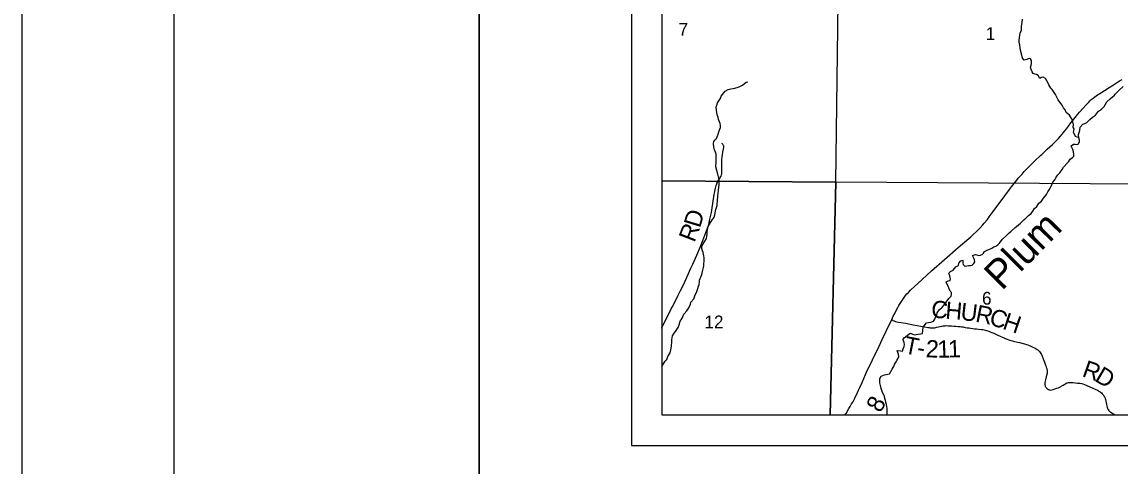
# Model space of a CAD drawing. Extents: x 0 to 34, y 0 to 22.
# Drawn here: x 0 to 3.604, y 13.932 to 15.391 of the extents above; entities that cross this region are included whole.
import ezdxf

# ---------------------------------------------------------------- set-up
doc = ezdxf.new("R2010")
doc.units = 0
for name, color, linetype in [('GM_X_Corporation', 7, 'Continuous'), ('GM_X_County_Road_Text', 7, 'Continuous'), ('GM_X_Interchange_Ramps', 7, 'Continuous'), ('GM_X_Interstate_Route', 7, 'Continuous'), ('GM_X_Major_Lake', 7, 'Continuous'), ('GM_X_Minor_Lake', 7, 'Continuous'), ('GM_X_Section', 7, 'Continuous'), ('GM_X_Township_Road_Text', 7, 'Continuous'), ('GM_X_Unincorporated_Text', 7, 'Continuous'), ('GM_X_US_Shield', 7, 'Continuous'), ('SH_Border', 7, 'Continuous'), ('SH_Cut_Line', 7, 'Continuous'), ('SH_Data', 7, 'Continuous')]:
    doc.layers.add(name, color=color, linetype=linetype)

msp = doc.modelspace()

# ---------------------------------------------------------------- linework, layer by layer
at = {"layer": 'GM_X_Corporation'}
for points in [[(2.8543, 14.4132), (2.8596, 14.424), (2.8643, 14.4338), (2.8689, 14.4433), (2.8739, 14.4525), (2.8782, 14.4597), (2.882, 14.4664), (2.8863, 14.4729), (2.8905, 14.479), (2.8952, 14.4859), (2.8998, 14.492), (2.9043, 14.4974), (2.9095, 14.5028), (2.9161, 14.5096), (2.9304, 14.5235), (2.9399, 14.5323), (2.9695, 14.5588), (2.9851, 14.5732), (3.0278, 14.6108), (3.0726, 14.6503), (3.0868, 14.6622), (3.1143, 14.6856), (3.1184, 14.6896), (3.1342, 14.7045), (3.1384, 14.7087), (3.1447, 14.7153), (3.1536, 14.7248), (3.158, 14.7299), (3.1683, 14.7424), (3.1744, 14.7504), (3.1878, 14.7686), (3.2255, 14.8198), (3.2405, 14.8403), (3.2473, 14.8493), (3.26, 14.8654), (3.2648, 14.8718), (3.2696, 14.8779), (3.2749, 14.8839), (3.282, 14.8914), (3.2895, 14.8995), (3.3142, 14.9252), (3.324, 14.935), (3.343, 14.9527), (3.3468, 14.9562), (3.365, 14.973), (3.3815, 14.9886), (3.3962, 15.0029), (3.4017, 15.0086), (3.4081, 15.0155), (3.4138, 15.022), (3.4183, 15.0275), (3.4225, 15.0332), (3.4275, 15.0399), (3.4343, 15.0491), (3.4423, 15.0599), (3.4473, 15.0666), (3.4646, 15.0882), (3.4707, 15.0951), (3.492, 15.1186), (3.4967, 15.1237), (3.5008, 15.1281), (3.5049, 15.1319), (3.5092, 15.1359), (3.5153, 15.1408), (3.5198, 15.1444), (3.5266, 15.1491), (3.5377, 15.1565), (3.5674, 15.1758), (3.5819, 15.185), (3.6016, 15.1975), (3.6101, 15.2025)], [(2.7012, 14.1), (2.7045, 14.1051), (2.7139, 14.1209), (2.7181, 14.1281), (2.7228, 14.1361), (2.7264, 14.1425), (2.7295, 14.148), (2.7332, 14.1551), (2.7422, 14.1734), (2.7457, 14.1809), (2.7499, 14.1902), (2.7569, 14.2063), (2.7684, 14.2334), (2.7714, 14.2407), (2.791, 14.2807), (2.8127, 14.3264), (2.8231, 14.3484), (2.836, 14.3748), (2.8543, 14.4132)]]:
    msp.add_lwpolyline(points, dxfattribs=at)
at = {"layer": 'GM_X_Interchange_Ramps'}
msp.add_lwpolyline([(2.1, 17.9098), (2.1, 14.1), (6.5113, 14.1), (6.5389, 15.3228), (6.5411, 15.4243), (6.5572, 16.1864), (6.5647, 16.5359), (6.5883, 17.471), (6.5943, 17.9356)], dxfattribs=at)
at = {"layer": 'GM_X_Interstate_Route'}
for points in [[(2.1, 14.3849), (2.1004, 14.3858), (2.131, 14.4482), (2.1359, 14.4579), (2.1537, 14.4931), (2.1604, 14.5068), (2.1683, 14.5234), (2.1749, 14.5375), (2.1955, 14.5819), (2.2015, 14.5954), (2.2143, 14.6251), (2.2263, 14.6537), (2.2343, 14.6731), (2.2444, 14.6989), (2.2488, 14.7105), (2.2511, 14.717), (2.2527, 14.7222), (2.2551, 14.7314), (2.2578, 14.7432), (2.2626, 14.7657), (2.2638, 14.7724), (2.2652, 14.7802), (2.2721, 14.8246), (2.2728, 14.8283), (2.2763, 14.8454), (2.2782, 14.8536), (2.279, 14.8563), (2.2799, 14.8593), (2.2811, 14.8621), (2.2818, 14.8633), (2.2934, 14.8834), (2.2941, 14.8848), (2.2957, 14.8887), (2.2961, 14.8905), (2.2964, 14.8923), (2.2967, 14.8982), (2.2968, 14.9107), (2.2969, 14.9325), (2.2972, 14.9385), (2.2981, 14.9495), (2.2987, 14.9547), (2.3001, 14.9636), (2.301, 14.9685), (2.3032, 14.9787), (2.3034, 14.9805), (2.3032, 14.9839), (2.3026, 14.9856), (2.3017, 14.9872), (2.3004, 14.9889), (2.2989, 14.9906), (2.2967, 14.9921)], [(2.8543, 14.4132), (2.8585, 14.4108), (2.8611, 14.4096), (2.8629, 14.4088), (2.8646, 14.4082), (2.8672, 14.4074), (2.8712, 14.4064), (2.8767, 14.4052), (2.8857, 14.4034), (2.8993, 14.401), (2.9147, 14.3984), (2.9261, 14.3964), (2.9735, 14.3878), (2.9775, 14.387), (2.9807, 14.3866), (2.9843, 14.3863), (2.9875, 14.3862), (2.9903, 14.3863), (2.9947, 14.3867), (2.9987, 14.3872), (3.0028, 14.3879), (3.008, 14.3891), (3.0138, 14.3905), (3.0226, 14.3925), (3.0259, 14.393), (3.0292, 14.3933), (3.0333, 14.3935), (3.0392, 14.3933), (3.0448, 14.3929), (3.05, 14.3924), (3.0584, 14.3918), (3.0651, 14.3915), (3.0721, 14.391), (3.0785, 14.3904), (3.0829, 14.3899), (3.0886, 14.3891), (3.0956, 14.3878), (3.1019, 14.3867), (3.108, 14.3857), (3.1134, 14.3849), (3.1204, 14.3838), (3.1262, 14.3832), (3.1322, 14.3825), (3.1394, 14.3819), (3.1491, 14.3808), (3.1536, 14.3803), (3.1577, 14.3796), (3.1616, 14.3786), (3.1657, 14.3775), (3.17, 14.3761), (3.1751, 14.3742), (3.1798, 14.3723), (3.1893, 14.3683), (3.2005, 14.3633), (3.2124, 14.3577), (3.2232, 14.3529), (3.2264, 14.3515), (3.2328, 14.3489), (3.2391, 14.3468), (3.2423, 14.3458), (3.2507, 14.3434), (3.2575, 14.3416), (3.2626, 14.3404), (3.2739, 14.3375), (3.2858, 14.3346), (3.2899, 14.3335), (3.2938, 14.3324), (3.297, 14.3313), (3.3012, 14.3298), (3.3061, 14.328), (3.3155, 14.3237), (3.3255, 14.3189), (3.3289, 14.317), (3.3316, 14.3154), (3.3341, 14.3134), (3.3368, 14.3108), (3.339, 14.3084), (3.3413, 14.3054), (3.3436, 14.3018), (3.3455, 14.2982), (3.348, 14.2927), (3.3511, 14.2846), (3.3554, 14.2736), (3.3592, 14.2638), (3.3609, 14.2594), (3.3617, 14.257), (3.363, 14.2524), (3.3637, 14.2497), (3.3641, 14.2475), (3.3644, 14.2454), (3.3645, 14.2431), (3.3644, 14.2407), (3.3642, 14.2385), (3.364, 14.2364), (3.3632, 14.2327), (3.3614, 14.2253), (3.3587, 14.2155), (3.3571, 14.2061), (3.3569, 14.2044), (3.357, 14.2011), (3.3572, 14.1991), (3.3577, 14.197), (3.3584, 14.1943), (3.3595, 14.192), (3.3602, 14.191), (3.361, 14.1898), (3.3623, 14.1883), (3.3636, 14.1872), (3.3642, 14.1864), (3.365, 14.1859), (3.3667, 14.1849), (3.3679, 14.1841), (3.3689, 14.1835), (3.37, 14.1831), (3.3723, 14.1822), (3.3752, 14.1817), (3.3802, 14.1824), (3.3843, 14.1836), (3.3893, 14.1853), (3.396, 14.1876), (3.4019, 14.1896), (3.406, 14.1912), (3.407, 14.1918), (3.4147, 14.1962), (3.4173, 14.1979), (3.4201, 14.1997), (3.4229, 14.2015), (3.4254, 14.2029), (3.4275, 14.2042), (3.4293, 14.205), (3.4316, 14.2058), (3.434, 14.2063), (3.4364, 14.2066), (3.4403, 14.2067), (3.4446, 14.2065), (3.4494, 14.2061), (3.4567, 14.2055), (3.4644, 14.2047), (3.4718, 14.2039), (3.4778, 14.203), (3.4819, 14.2019), (3.4865, 14.2005), (3.492, 14.1983), (3.5049, 14.1924), (3.5244, 14.1834), (3.5297, 14.1809), (3.5363, 14.1772), (3.5382, 14.1761), (3.54, 14.1748), (3.5428, 14.1725), (3.5455, 14.1695), (3.5476, 14.1671), (3.5499, 14.1638), (3.5516, 14.161), (3.5532, 14.1579), (3.5547, 14.1545), (3.556, 14.1505), (3.5572, 14.1456), (3.5583, 14.1406), (3.5591, 14.1352), (3.5605, 14.1287), (3.5614, 14.1249)], [(3.5614, 14.1249), (3.562, 14.1228), (3.5628, 14.1208), (3.5636, 14.1192), (3.5649, 14.1174), (3.5668, 14.1147), (3.5684, 14.1129), (3.5706, 14.1109), (3.5733, 14.1088), (3.5763, 14.1068), (3.5806, 14.1041), (3.5855, 14.1014), (3.588, 14.1)]]:
    msp.add_lwpolyline(points, dxfattribs=at)
at = {"layer": 'GM_X_Minor_Lake'}
msp.add_lwpolyline([(2.684, 15.8792), (3.688, 15.8589), (3.6743, 14.926), (3.6733, 14.8581), (2.6707, 14.8651)], close=True, dxfattribs=at)
at = {"layer": 'GM_X_Township_Road_Text'}
for points in [[(3.4681, 15.0116), (3.4624, 15.0122), (3.4575, 15.0152), (3.4548, 15.0201), (3.4512, 15.0277), (3.4523, 15.0341), (3.4526, 15.0406), (3.4502, 15.0455), (3.4509, 15.0528), (3.4488, 15.0634), (3.4453, 15.0725), (3.4414, 15.0796), (3.4379, 15.0853), (3.4322, 15.0894), (3.4268, 15.0939), (3.4233, 15.1022), (3.4182, 15.1094), (3.4132, 15.1173), (3.4062, 15.1278), (3.4008, 15.1357), (3.3962, 15.1437), (3.3915, 15.1531), (3.3857, 15.1629), (3.3814, 15.1697), (3.3764, 15.1742), (3.3733, 15.1795), (3.3702, 15.1844), (3.3682, 15.1904), (3.3636, 15.1983), (3.3593, 15.2051), (3.3516, 15.21), (3.3452, 15.2087), (3.34, 15.2052), (3.3353, 15.215), (3.3296, 15.2188), (3.3235, 15.2198), (3.3185, 15.2224), (3.315, 15.2277), (3.3115, 15.2352), (3.3103, 15.2428), (3.3117, 15.2493), (3.3135, 15.255), (3.3126, 15.2649), (3.3099, 15.2698), (3.3049, 15.2717), (3.2974, 15.2681), (3.2895, 15.2653), (3.2833, 15.2725), (3.2801, 15.2861), (3.2777, 15.2941), (3.2764, 15.3055), (3.2744, 15.3165), (3.2731, 15.3241), (3.2726, 15.3317), (3.275, 15.3481), (3.2761, 15.3542), (3.2797, 15.3645), (3.2804, 15.3699), (3.2807, 15.3763), (3.282, 15.3901), (3.2837, 15.4004)], [(2.2317, 14.5613), (2.2338, 14.5712), (2.2366, 14.5846), (2.2377, 14.5903), (2.238, 14.5968), (2.2386, 14.6048), (2.2385, 14.6158), (2.238, 14.6227), (2.2371, 14.6284), (2.2352, 14.634), (2.2332, 14.639), (2.2308, 14.6465), (2.2315, 14.6542), (2.2411, 14.6707), (2.2462, 14.6799), (2.2476, 14.6868), (2.2483, 14.6944), (2.2486, 14.702), (2.2496, 14.7085), (2.2517, 14.7192), (2.2565, 14.7269), (2.2599, 14.7322), (2.2643, 14.7392), (2.2721, 14.7499), (2.2739, 14.758), (2.2764, 14.769), (2.277, 14.7748), (2.2818, 14.7878), (2.2817, 14.7927), (2.2827, 14.8034), (2.283, 14.8095), (2.2833, 14.8148), (2.2835, 14.8213), (2.2846, 14.8278), (2.2859, 14.8385), (2.2866, 14.8484), (2.2876, 14.8556), (2.2879, 14.8617), (2.2877, 14.8739), (2.2861, 14.8826), (2.2837, 14.8906), (2.2804, 14.9035), (2.2776, 14.9148), (2.2772, 14.9205), (2.2778, 14.9266), (2.2781, 14.9373), (2.2779, 14.9457), (2.2778, 14.9567), (2.2758, 14.9631), (2.2726, 14.9715), (2.2702, 14.9798), (2.2693, 14.9916), (2.2707, 14.9985), (2.2744, 15.0042), (2.2797, 15.0085), (2.2819, 15.0139), (2.2844, 15.0227), (2.288, 15.0337), (2.2906, 15.0395), (2.292, 15.0448), (2.2919, 15.0513), (2.2911, 15.0574), (2.2895, 15.0631), (2.286, 15.0706), (2.2843, 15.0782), (2.2816, 15.0858), (2.2791, 15.1017), (2.2785, 15.1116), (2.28, 15.1177), (2.2825, 15.125), (2.2932, 15.1423), (2.2947, 15.1473), (2.3032, 15.1581), (2.3081, 15.1638), (2.3171, 15.1693), (2.3261, 15.171), (2.3341, 15.1722), (2.3394, 15.1735), (2.3503, 15.1771), (2.3578, 15.1806), (2.3646, 15.1834), (2.3769, 15.1938), (2.3818, 15.1947)], [(3.5328, 15.0978), (3.5425, 15.1052), (3.5515, 15.1129), (3.5559, 15.1206), (3.5607, 15.1283), (3.5711, 15.1391), (3.5798, 15.1461), (3.5846, 15.1488), (3.588, 15.1538), (3.6003, 15.1673), (3.6137, 15.179)], [(3.043, 14.514), (3.0391, 14.5231), (3.0348, 14.5306), (3.0328, 14.5371), (3.04, 14.5406), (3.0456, 14.5418), (3.0467, 14.5468), (3.0462, 14.5518), (3.0446, 14.5574), (3.0423, 14.5654), (3.0467, 14.5712), (3.0565, 14.5755), (3.065, 14.5871), (3.0733, 14.5914), (3.0751, 14.5983), (3.0807, 14.6067), (3.0878, 14.608), (3.088, 14.5992), (3.0888, 14.5939), (3.0942, 14.5883), (3.1006, 14.5895), (3.1063, 14.5907), (3.1127, 14.5912), (3.1184, 14.5917), (3.124, 14.5975), (3.1269, 14.6032), (3.1264, 14.6093), (3.1237, 14.6154), (3.119, 14.6237), (3.1288, 14.6269), (3.1338, 14.6266), (3.1391, 14.624), (3.1455, 14.6245), (3.1508, 14.6272), (3.156, 14.6315), (3.1593, 14.6368), (3.1702, 14.6427), (3.1781, 14.6459), (3.1834, 14.6475), (3.1898, 14.6525), (3.1962, 14.6545), (3.203, 14.6584), (3.2074, 14.6635), (3.2178, 14.6773), (3.2316, 14.6912), (3.2399, 14.6978), (3.2466, 14.7037), (3.2593, 14.7156), (3.2642, 14.7188), (3.2709, 14.7246), (3.2769, 14.73), (3.2888, 14.742), (3.2944, 14.7463), (3.303, 14.7548), (3.3124, 14.7618), (3.3172, 14.7691), (3.3231, 14.7779), (3.331, 14.7845), (3.3373, 14.7953), (3.3455, 14.8022), (3.3525, 14.8122), (3.3618, 14.8238), (3.367, 14.8326), (3.3714, 14.8395), (3.3751, 14.8472), (3.3784, 14.8537), (3.3836, 14.8649), (3.3891, 14.8729), (3.3932, 14.8795), (3.3991, 14.8887), (3.4055, 14.8956), (3.4136, 14.9068), (3.4181, 14.9137), (3.4296, 14.9268), (3.4345, 14.9315), (3.4404, 14.9399), (3.4471, 14.9454), (3.452, 14.9504), (3.4519, 14.9561), (3.4514, 14.9645), (3.4486, 14.9724), (3.4459, 14.9789), (3.4432, 14.9841), (3.4514, 14.99), (3.4567, 14.9897), (3.4624, 14.9882), (3.4673, 14.991), (3.471, 14.9979), (3.4705, 15.0032), (3.4682, 15.01), (3.4676, 15.0214), (3.4694, 15.0283), (3.4712, 15.0356), (3.4733, 15.0459), (3.4811, 15.0555), (3.4883, 15.0579), (3.4947, 15.0614), (3.5044, 15.0707), (3.5137, 15.0789), (3.5227, 15.0855), (3.5328, 15.0978)], [(2.1, 14.2596), (2.1035, 14.2647), (2.1113, 14.2767), (2.1165, 14.2821), (2.1201, 14.2916), (2.1268, 14.3043), (2.1297, 14.3142), (2.1314, 14.3264), (2.1331, 14.3409), (2.1326, 14.347), (2.1333, 14.3535), (2.1354, 14.3604), (2.1402, 14.3692), (2.1451, 14.3738), (2.1532, 14.3877), (2.1565, 14.3957), (2.1605, 14.4076), (2.1634, 14.4126), (2.1668, 14.4179), (2.1719, 14.4313), (2.1816, 14.4418), (2.186, 14.4491), (2.1937, 14.4633), (2.1952, 14.4702), (2.2052, 14.481), (2.2085, 14.4909), (2.2143, 14.5055), (2.2176, 14.515), (2.2201, 14.5231), (2.2223, 14.5288), (2.223, 14.5368), (2.2236, 14.5425), (2.2287, 14.5555), (2.2317, 14.5613)], [(2.8399, 14.1), (2.8396, 14.1033), (2.8399, 14.1109), (2.8398, 14.1212), (2.8377, 14.1341), (2.8349, 14.142), (2.8337, 14.1473), (2.8313, 14.1545), (2.8301, 14.1613), (2.8266, 14.1693), (2.8234, 14.1772), (2.8202, 14.1867), (2.8175, 14.1966), (2.8154, 14.206), (2.8149, 14.2125), (2.8156, 14.2197), (2.82, 14.227), (2.8306, 14.2322), (2.8419, 14.2338), (2.8468, 14.2347), (2.8553, 14.25), (2.8627, 14.2608), (2.8638, 14.2662), (2.8667, 14.2711), (2.8708, 14.2792), (2.8749, 14.2842), (2.8781, 14.2923), (2.8769, 14.3002), (2.8746, 14.3051), (2.8722, 14.3112), (2.8836, 14.3102), (2.8896, 14.3092), (2.8918, 14.3176), (2.8947, 14.3249), (2.8961, 14.331), (2.8949, 14.3382), (2.8933, 14.3431), (2.8917, 14.3488), (2.8947, 14.3538), (2.9108, 14.3658), (2.916, 14.3686), (2.9221, 14.3649), (2.9301, 14.3631), (2.935, 14.3639), (2.9407, 14.3652), (2.9494, 14.3668), (2.9554, 14.368), (2.956, 14.3764), (2.9578, 14.3886), (2.9685, 14.4025), (2.9753, 14.4037), (2.9829, 14.405), (2.9916, 14.4078), (2.996, 14.4147), (2.9989, 14.4231), (3.0026, 14.4285), (3.004, 14.435), (3.0111, 14.4465), (3.0189, 14.4524), (3.0286, 14.4639), (3.0331, 14.4701), (3.042, 14.4828), (3.0498, 14.4905), (3.0505, 14.4959), (3.05, 14.502), (3.0461, 14.5072), (3.043, 14.514)]]:
    msp.add_lwpolyline(points, dxfattribs=at)
at = {"layer": 'GM_X_Unincorporated_Text'}
for points in [[(2.1, 15.8894), (2.1, 14.8693), (2.6707, 14.8651), (2.684, 15.8792)], [(2.1, 14.8693), (2.1, 14.1), (2.6521, 14.1), (2.6707, 14.8651)], [(2.6521, 14.1), (3.6651, 14.1), (3.6733, 14.8581), (2.6707, 14.8651)]]:
    msp.add_lwpolyline(points, close=True, dxfattribs=at)
at = {"layer": 'SH_Border'}
for points in [[(0.5, 21.5), (1.5, 21.5), (1.5, 0.5), (0.5, 0.5)], [(1.5, 21.5), (33.5, 21.5), (33.5, 0.5), (1.5, 0.5)]]:
    msp.add_lwpolyline(points, close=True, dxfattribs=at)
at = {"layer": 'SH_Cut_Line'}
for points in [[(0, 0), (34, 0), (34, 22), (0, 22)], [(2.1, 17.9098), (2.1, 14.1), (8.9, 14.1), (8.9, 17.8921), (8.5492, 17.9006), (8.3297, 17.9059), (7.6027, 17.9156), (6.5943, 17.9356), (6.24, 17.9427), (6.0729, 17.9463), (5.6339, 17.9555), (5.3871, 17.9608), (4.994, 17.969), (4.9368, 17.9702), (4.9267, 17.9702), (4.5919, 17.9719), (4.4481, 17.9728), (4.1825, 17.9744), (3.7128, 17.9822), (3.7063, 17.8588), (3.604, 17.8577), (2.9484, 17.8857), (2.6711, 17.8975), (2.4376, 17.9025)]]:
    msp.add_lwpolyline(points, close=True, dxfattribs=at)
at = {"layer": 'SH_Data'}
for p, q in [((2, 21), (2, 14)), ((2.1, 20.9), (2.1, 14.1)), ((2.1, 14.1), (8.9, 14.1)), ((2.1, 14.1), (2.1, 14.1)), ((2, 14), (9, 14))]:
    msp.add_line(p, q, dxfattribs=at)

# ---------------------------------------------------------------- texts
at = {"layer": 'GM_X_County_Road_Text'}
for s, height, p in [('7', 0.0419, (2.1549, 15.3458)), ('1', 0.0419, (3.1628, 15.332)), ('6', 0.0419, (3.1507, 14.4624)), ('12', 0.04186, (2.2399, 14.3848))]:
    msp.add_text(s, height=height, rotation=0, dxfattribs=at).set_placement(p)
at = {"layer": 'GM_X_Major_Lake'}
msp.add_text('8', height=0.0568, rotation=61.6459, dxfattribs=at).set_placement((2.8175, 14.1044))
at = {"layer": 'GM_X_Section'}
for s, rotation, p in [('D', 73.0228, (2.2249, 14.712)), ('R', 68.8871, (2.2066, 14.6644)), ('C', 355.7028, (2.9824, 14.4201)), ('H', 355.2554, (3.0288, 14.4166)), ('U', 353.2491, (3.0781, 14.4125)), ('R', 348.5867, (3.1265, 14.4068)), ('C', 342.3587, (3.1707, 14.398)), ('H', 341.2229, (3.2149, 14.3839)), ('T', 349.0263, (2.8919, 14.3034)), ('2', 356.8975, (2.965, 14.29)), ('1', 1.0514, (3.0045, 14.288)), ('1', 1.2599, (3.0397, 14.2887)), ('-', 349.385, (2.934, 14.2953)), ('R', 340.4924, (3.4761, 14.2276)), ('D', 329.2655, (3.5174, 14.2133))]:
    msp.add_text(s, height=0.0568, rotation=rotation, dxfattribs=at).set_placement(p)
at = {"layer": 'GM_X_US_Shield'}
msp.add_text('Plum', height=0.09469, rotation=45.2251, dxfattribs=at).set_placement((3.2158, 14.5059))

doc.saveas('drawing.dxf')
